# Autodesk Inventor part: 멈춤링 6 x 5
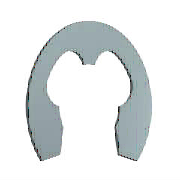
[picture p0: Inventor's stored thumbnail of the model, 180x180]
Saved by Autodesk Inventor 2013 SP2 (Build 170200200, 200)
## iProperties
Created: 2012-02
Part Number: 멈춤링 6 x 5
Material: 강철, 연강
Description: 스프링 리테이닝 링
Document SubType Name: Modeling
Standard: JIS B 2805
Designer: mduedu
Standards Organization: JIS
Language: ko-KR
Size Designation: 5
Categories: <MemberInstance><Categories><Category DisplayName="샤프트 부품" InternalName="7f7aeb1f-a693-4053-b835-cee3144e0d98" Mnemonic="SHFT"><Category DisplayName="써클립" Inter
Density: 1 g/cm^3
IsCustomPart: 1
Author: mduedu
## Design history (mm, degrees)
sketch "스케치1"
  geometry: L1 (-0.5, 0.024)-(0, 0.024) reference; L2 (-3.206, 0)-(3.486, 0) reference; L3 (-2.291, -3.976)-(2.291, -3.976); L4 (0, 1.949)-(0, -3.479) reference; L5 (-3, -1.976)-(-2.51, -1.976); L6 (-0.5, 0.024)-(-0.5, 0.509); L7 (0, 2.524)-(2.53, 2.524); L8 (-2.291, -3.976)-(-3.051, -6.131); L9 (0, -0.476)-(-1.278, -0.476); L10 (2.291, -3.976)-(3.051, -6.131); L11 (3, -1.976)-(2.51, -1.976); L12 (0.5, 0.024)-(0.5, 0.509); C1 r 3 at (0, -2.976); A1 r 2.5 centre (0, -2.976) between (-2.368, -2.174) and (-2.291, -3.976); A2 r 0.5 centre (0, 0.024) between (-0.5, 0.024) and (0.5, 0.024); A3 r 5.5 centre (0, -2.976) between (4.351, -6.34) and (-4.351, -6.34); A4 r 4 centre (0, -2.976) between (-1, 0.897) and (-3.529, -1.094); A5 r 0.4 centre (-0.9, 0.509) between (-0.5, 0.509) and (-1, 0.897); A6 r 0.6 centre (-3, -1.376) between (-3.529, -1.094) and (-3, -1.976); A7 r 0.15 centre (-2.51, -2.126) between (-2.368, -2.174) and (-2.51, -1.976); A8 r 0.75 centre (-3.758, -5.881) between (-4.351, -6.34) and (-3.051, -6.131); A9 r 0.75 centre (3.758, -5.881) between (3.051, -6.131) and (4.351, -6.34); A10 r 2.5 centre (0, -2.976) between (2.291, -3.976) and (2.368, -2.174); A11 r 0.15 centre (2.51, -2.126) between (2.51, -1.976) and (2.368, -2.174); A12 r 0.6 centre (3, -1.376) between (3, -1.976) and (3.529, -1.094); A13 r 4 centre (0, -2.976) between (3.529, -1.094) and (1, 0.897); A14 r 0.4 centre (0.9, 0.509) between (1, 0.897) and (0.5, 0.509); 1 further point
  constraints: 30 point on circle, 20 end point, 15 centre point, 13 symmetric about line, 12 tangent, 8 point on line, 4 parallel, 2 coincident, 2 horizontal, 1 concentric, 1 perpendicular, 1 vertical alignment, 9 other
  dimensions: "d0" = 6 diameter of C1 (= WD); "d3" = 1 distance from line of A1.centre L3 (= 0.2 x ND); "d4" = 0.5 radius of A2 (= 0.1 x ND); "d5" = 11 diameter of A3 (= SD2); "d8" = 4 radius of A4 (= 0.8 x ND); "d9" = 1 distance from line of A1.centre L5 (= 0.2 x ND); "d10" = 0.4 radius of A5 (= 0.08 x ND); "d11" = 0.6 radius of A6 (= 0.12 x ND); "d12" = 0.15 radius of A7 (= 0.03 x ND); "d13" = 0.75 radius of A8 (= 0.15 x ND); "d14" = 2.5 distance from line of A1.centre L9 (= 0.5 x ND); "d15" = 2.5 radius of A1 (= 0.5 x ND)
extrude "본체" new body sketch "스케치1" distance "d16" = 0.6 (= SD); taper "d17" = 0 deg
workaxis "Work Axis1"
workaxis "Work Axis2"
workplane "Work Plane1"
body "Solid1"
other parameters: "ND" = 5 [user parameter; used in 14 equation terms], "SD" = 0.6 [user parameter; used in 1 equation term], "WD" = 6 (= WDMIN) [user parameter; used in 1 equation term], "d1" = 8 (= 1.6 x ND), "d2" = 5 (= ND), "SD2" = 11 [user parameter; used in 1 equation term], "d6" = 5 (= ND), "d7" = 0.75 (= 0.15 x ND), "d18" = 0, "d19" = 0, "d27" = 0, "d28" = 0, "WDMIN" = 6 [user parameter; used in 1 equation term], "SNB" = 0.7 [user parameter], "WDMAX" = 8 [user parameter], "BUBRMI" = 1.2 [user parameter]
